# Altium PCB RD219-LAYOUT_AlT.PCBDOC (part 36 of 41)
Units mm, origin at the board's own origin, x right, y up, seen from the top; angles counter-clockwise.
Board outline 209.75 x 159.97 mm, 2 copper layers (TOP, BOTTOM), stack 0 mm thick; 398 components, 199 nets, 1469 pads, 0 vias.
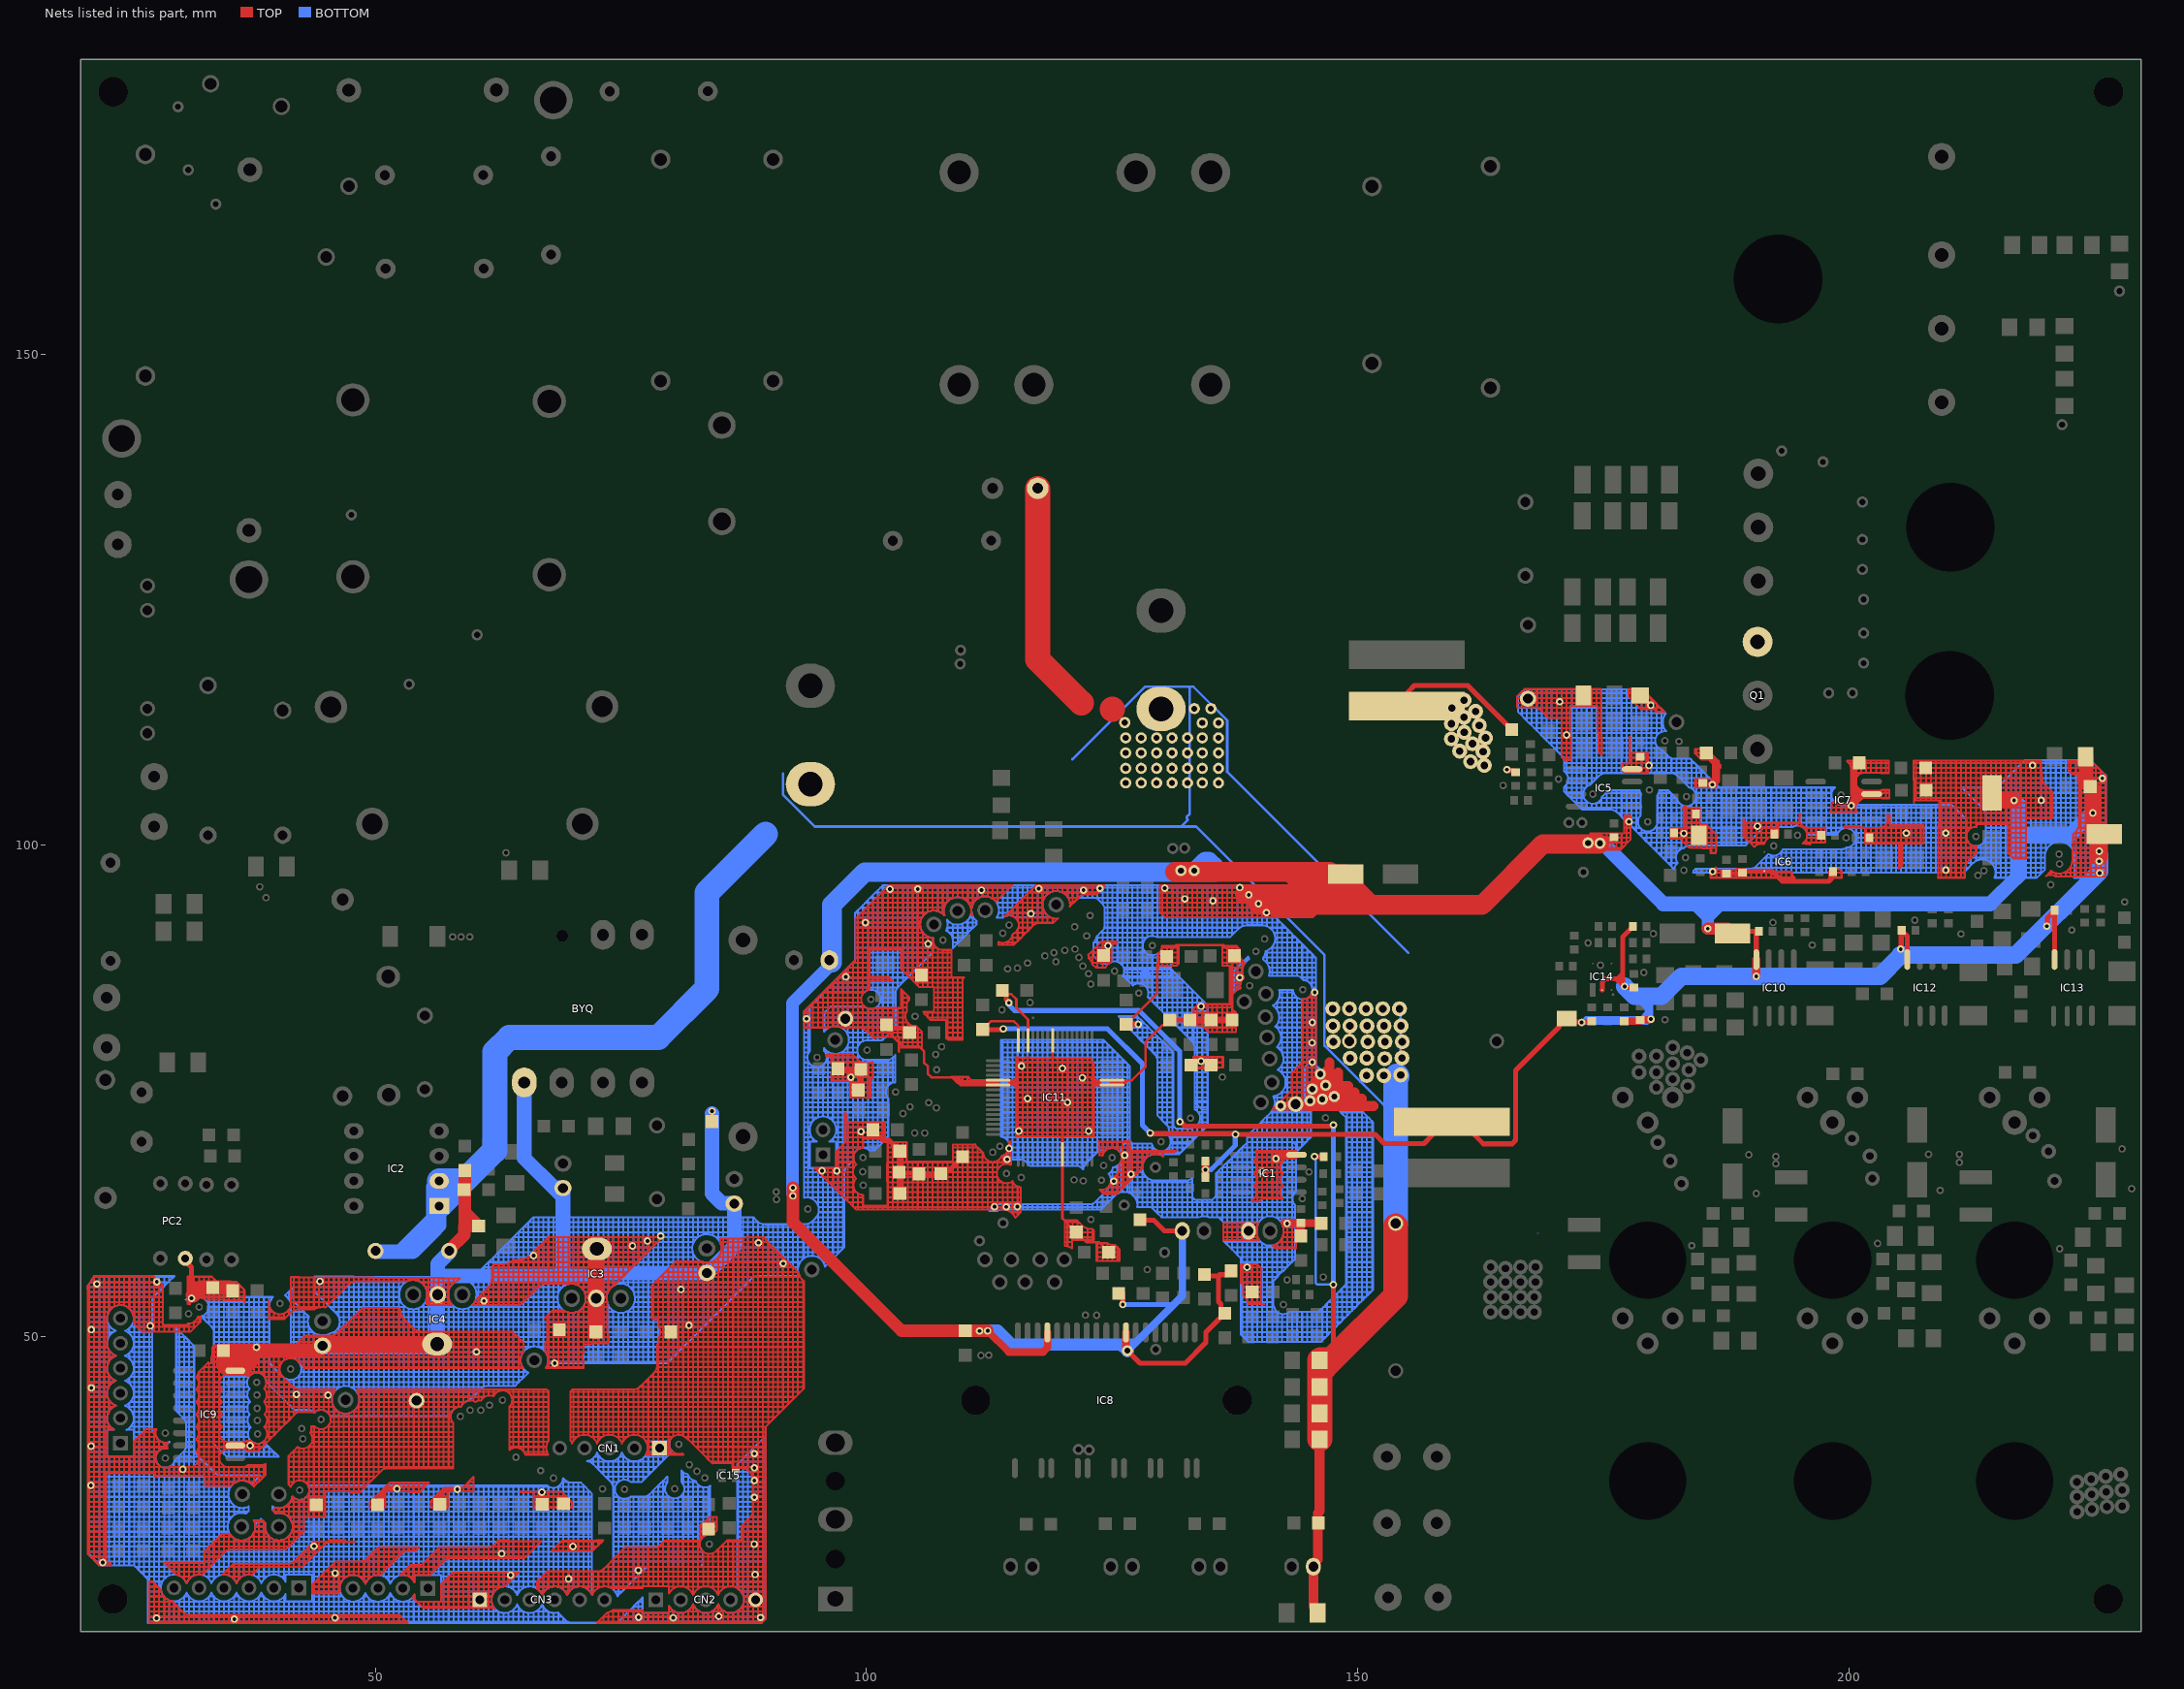
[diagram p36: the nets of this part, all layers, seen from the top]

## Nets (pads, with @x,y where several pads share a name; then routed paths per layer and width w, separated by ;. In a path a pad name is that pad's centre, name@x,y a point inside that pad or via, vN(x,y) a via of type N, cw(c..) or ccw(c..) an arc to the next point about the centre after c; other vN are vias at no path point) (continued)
GND: (continued)
  BOTTOM w0.203: 173.289,108.392 173.289,108.9 ; 173.289,108.392 173.797,108.392 ; 173.289,108.9 173.797,108.9 ; 173.289,108.9 173.289,109.408 ; 173.289,109.408 173.797,109.408 ; 173.289,109.408 173.289,109.916 ; 173.289,109.916 173.797,109.916 ; 173.289,109.916 173.289,110.424 ; 173.289,110.424 173.797,110.424 ; 173.289,110.424 173.289,110.932 ; 173.289,110.932 173.797,110.932 ; 173.289,110.932 173.289,111.44 ; 173.289,111.44 173.797,111.44 ; 173.289,111.44 173.289,111.948 ; 173.289,111.948 173.797,111.948 ; 173.289,111.948 173.289,112.456 ; 173.289,112.456 173.797,112.456 ; 173.289,112.456 173.289,112.964 ; 173.289,112.964 173.797,112.964 ; 173.289,112.964 173.289,113.472 ; 173.289,113.472 173.797,113.472 ; 173.289,113.472 173.289,113.98 ; 173.289,113.98 173.797,113.98 ; 173.289,113.98 173.289,114.488 ; 173.289,114.488 173.797,114.488 ; 173.289,114.488 173.289,114.996 ; 173.289,114.996 173.797,114.996 ; 173.289,114.996 173.289,115.504 ; 173.289,115.504 173.797,115.504 ; 173.289,115.504 173.289,115.885 ; 173.289,115.885 173.797,115.885 ; 173.505,104.328 ccw(c173.924,105.217) 173.797,104.243 ; 173.797,103.667 173.797,103.82 ; 173.797,103.667 174.305,103.667 ; 173.797,103.82 174.305,103.82 ; 173.797,103.82 173.797,104.243 ; 173.797,104.243 ccw(c173.924,105.217) 173.804,104.242 ccw(c173.924,105.217) 174.305,104.311 ; 173.797,106.3 173.797,106.36 ; 173.797,106.3 173.857,106.36 ; 173.797,106.36 173.797,106.868 ; 173.797,106.36 173.857,106.36 ; 173.797,106.868 173.797,107.376 ; 173.797,106.868 174.305,106.868 ; 173.797,107.376 173.797,107.884 ; 173.797,107.376 174.305,107.376 ; 173.797,107.884 173.797,108.392 ; 173.797,107.884 174.305,107.884 ; 173.797,108.392 173.797,108.9 ; 173.797,108.392 174.305,108.392 ; 173.797,108.9 174.305,108.9 ; 173.797,108.9 173.797,109.408 ; 173.797,109.408 174.305,109.408 ; 173.797,109.408 173.797,109.916 ; 173.797,109.916 174.305,109.916 ; 173.797,109.916 173.797,110.424 ; 173.797,110.424 174.305,110.424 ; 173.797,110.424 173.797,110.932 ; 173.797,110.932 174.305,110.932 ; 173.797,110.932 173.797,111.44 ; 173.797,111.44 174.305,111.44 ; 173.797,111.44 173.797,111.948 ; 173.797,111.948 174.305,111.948 ; 173.797,111.948 173.797,112.456 ; 173.797,112.456 174.305,112.456 ; 173.797,112.456 173.797,112.964 ; 173.797,112.964 174.305,112.964 ; 173.797,112.964 173.797,113.472 ; 173.797,113.472 174.305,113.472 ; 173.797,113.472 173.797,113.98 ; 173.797,113.98 174.305,113.98 ; 173.797,113.98 173.797,114.488 ; 173.797,114.488 174.305,114.488 ; 173.797,114.488 173.797,114.996 ; 173.797,114.996 174.305,114.996 ; 173.797,114.996 173.797,115.504 ; 173.797,115.504 174.305,115.504 ; 173.797,115.504 173.797,115.885 ; 173.797,115.885 174.305,115.885 ; 173.857,106.36 174.305,106.808 ; 174.305,103.667 174.813,103.667 ; 174.305,103.667 174.305,103.82 ; 174.305,103.82 174.813,103.82 ; 174.305,103.82 174.305,104.311 ; 174.305,104.311 ccw(c173.924,105.217) 174.343,104.328 ; 174.305,106.808 174.305,106.868 ; 174.305,106.808 174.365,106.868 ; 174.305,106.868 174.305,107.376 ; 174.305,106.868 174.365,106.868 ; 174.305,107.376 174.305,107.884 ; 174.305,107.376 174.813,107.376 ; 174.305,107.884 174.305,108.392 ; 174.305,107.884 174.813,107.884 ; 174.305,108.392 174.305,108.9 ; 174.305,108.392 174.813,108.392 ; 174.305,108.9 174.813,108.9 ; 174.305,108.9 174.305,109.408 ; 174.305,109.408 174.813,109.408 ; 174.305,109.408 174.305,109.916 ; 174.305,109.916 174.813,109.916 ; 174.305,109.916 174.305,110.424 ; 174.305,110.424 174.813,110.424 ; 174.305,110.424 174.305,110.932 ; 174.305,110.932 174.813,110.932 ; 174.305,110.932 174.305,111.44 ; 174.305,111.44 174.813,111.44 ; 174.305,111.44 174.305,111.948 ; 174.305,111.948 174.813,111.948 ; 174.305,111.948 174.305,112.456 ; 174.305,112.456 174.813,112.456 ; 174.305,112.456 174.305,112.964 ; 174.305,112.964 174.813,112.964 ; 174.305,112.964 174.305,113.472 ; 174.305,113.472 174.813,113.472 ; 174.305,113.472 174.305,113.98 ; 174.305,113.98 174.813,113.98 ; 174.305,113.98 174.305,114.488 ; 174.305,114.488 174.813,114.488 ; 174.305,114.488 174.305,114.996 ; 174.305,114.996 174.813,114.996 ; 174.305,114.996 174.305,115.504 ; 174.305,115.504 174.813,115.504 ; 174.305,115.504 174.305,115.885 ; 174.305,115.885 174.813,115.885 ; 174.343,104.328 ccw(c173.924,105.217) 174.813,104.798 ; 174.343,104.328 174.813,104.328 ; 174.365,106.868 174.589,107.092 ; 174.589,107.092 cw(c175.194,106.487) 174.813,107.253 ; 174.589,107.092 cw(c175.194,106.487) 174.813,107.253 ; 174.813,103.667 174.813,103.82 ; 174.813,103.667 175.321,103.667 ; 174.813,103.82 174.813,104.328 ; 174.813,103.82 175.321,103.82 ; 174.813,104.328 175.321,104.328 ; 174.813,104.328 174.813,104.798 ; 174.813,104.798 ccw(c173.924,105.217) 174.83,104.836 ; 174.813,107.253 cw(c175.194,106.487) 175.194,107.343 ; 174.813,107.253 cw(c175.194,106.487) 175.194,107.343 ; 174.813,107.253 174.813,107.376 ; 174.813,107.376 174.813,107.884 ; 174.813,107.376 175.321,107.376 ; 174.813,107.884 174.813,108.392 ; 174.813,107.884 175.321,107.884 ; 174.813,108.392 174.813,108.9 ; 174.813,108.392 175.321,108.392 ; 174.813,108.9 175.321,108.9 ; 174.813,108.9 174.813,109.408 ; 174.813,109.408 175.321,109.408 ; 174.813,109.408 174.813,109.916 ; 174.813,109.916 175.321,109.916 ; 174.813,109.916 174.813,110.424 ; 174.813,110.424 175.321,110.424 ; 174.813,110.424 174.813,110.932 ; 174.813,110.932 175.321,110.932 ; 174.813,110.932 174.813,111.44 ; 174.813,111.44 175.321,111.44 ; 174.813,111.44 174.813,111.948 ; 174.813,111.948 175.321,111.948 ; 174.813,111.948 174.813,112.456 ; 174.813,112.456 175.321,112.456 ; 174.813,112.456 174.813,112.964 ; 174.813,112.964 175.321,112.964 ; 174.813,112.964 174.813,113.472 ; 174.813,113.472 175.321,113.472 ; 174.813,113.472 174.813,113.98 ; 174.813,113.98 175.321,113.98 ; 174.813,113.98 174.813,114.488 ; 174.813,114.488 175.321,114.488 ; 174.813,114.488 174.813,114.996 ; 174.813,114.996 175.321,114.996 ; 174.813,114.996 174.813,115.504 ; 174.813,115.504 175.321,115.504 ; 174.813,115.504 174.813,115.885 ; 174.813,115.885 175.321,115.885 ; 174.83,104.836 175.321,104.836 ; 175.194,107.343 175.321,107.343 ; 175.261,105.344 175.321,105.344 ; 175.261,105.344 175.321,105.404 ; 175.321,103.667 175.321,103.82 ; 175.321,103.667 175.545,103.667 ; 175.321,103.82 175.321,104.328 ; 175.321,103.82 175.829,103.82 ; 175.321,104.328 175.321,104.836 ; 175.321,104.328 175.829,104.328 ; 175.321,104.836 175.829,104.836 ; 175.321,104.836 175.321,105.344 ; 175.321,105.344 175.829,105.344 ; 175.321,105.344 175.321,105.404 ; 175.321,105.404 175.548,105.631 175.829,105.631 ; 175.321,107.343 175.321,107.376 ; 175.321,107.343 175.829,107.343 ; 175.321,107.376 175.321,107.884 ; 175.321,107.376 175.829,107.376 ; 175.321,107.884 175.321,108.392 ; 175.321,107.884 175.829,107.884 ; 175.321,108.392 175.321,108.9 ; 175.321,108.392 175.829,108.392 ; 175.321,108.9 175.321,109.408 ; 175.321,108.9 175.829,108.9 ; 175.321,109.408 175.321,109.916 ; 175.321,109.408 175.829,109.408 ; 175.321,109.916 175.321,110.424 ; 175.321,109.916 175.829,109.916 ; 175.321,110.424 175.321,110.932 ; 175.321,110.424 175.829,110.424 ; 175.321,110.932 175.321,111.44 ; 175.321,110.932 175.829,110.932 ; 175.321,111.44 175.321,111.948 ; 175.321,111.44 175.829,111.44 ; 175.321,111.948 175.321,112.456 ; 175.321,111.948 175.829,111.948 ; 175.321,112.456 175.321,112.964 ; 175.321,112.456 175.829,112.456 ; 175.321,112.964 175.321,113.472 ; 175.321,112.964 175.829,112.964 ; 175.321,113.472 175.321,113.98 ; 175.321,113.472 175.829,113.472 ; 175.321,113.98 175.321,114.488 ; 175.321,113.98 175.829,113.98 ; 175.321,114.488 175.321,114.996 ; 175.321,114.488 175.829,114.488 ; 175.321,114.996 175.321,115.504 ; 175.321,114.996 175.829,114.996 ; 175.321,115.504 175.321,115.885 ; 175.321,115.504 175.829,115.504 ; 175.321,115.885 175.829,115.885 ; 175.545,103.667 cw(c175.545,102.315) 175.826,103.637 ; 175.545,103.667 cw(c175.545,102.315) 175.826,103.637 ; 175.826,103.637 cw(c175.545,102.315) 175.829,103.637 ; 175.826,103.637 cw(c175.545,102.315) 175.829,103.637 ; 175.829,103.637 cw(c175.545,102.315) 176.337,103.411 ; 175.829,103.637 cw(c175.545,102.315) 176.337,103.411 ; 175.829,103.637 175.829,103.82 ; 175.829,103.82 176.337,103.82 ; 175.829,103.82 175.829,104.328 ; 175.829,104.328 175.829,104.836 ; 175.829,104.328 176.337,104.328 ; 175.829,104.836 176.337,104.836 ; 175.829,104.836 175.829,105.344 ; 175.829,105.344 176.337,105.344 ; 175.829,105.344 175.829,105.631 ; 175.829,105.631 176.337,105.631 ; 175.829,107.343 175.829,107.376 ; 175.829,107.343 176.337,107.343 ; 175.829,107.376 175.829,107.884 ; 175.829,107.376 176.337,107.376 ; 175.829,107.884 175.829,108.392 ; 175.829,107.884 176.337,107.884 ; 175.829,108.392 175.829,108.9 ; 175.829,108.392 176.337,108.392 ; 175.829,108.9 175.829,109.408 ; 175.829,108.9 176.337,108.9 ; 175.829,109.408 175.829,109.916 ; 175.829,109.408 176.337,109.408 ; 175.829,109.916 175.829,110.424 ; 175.829,109.916 176.337,109.916 ; 175.829,110.424 175.829,110.932 ; 175.829,110.424 176.337,110.424 ; 175.829,110.932 175.829,111.44 ; 175.829,110.932 176.337,110.932 ; 175.829,111.44 175.829,111.948 ; 175.829,111.44 176.337,111.44 ; 175.829,111.948 175.829,112.456 ; 175.829,111.948 176.337,111.948 ; 175.829,112.456 175.829,112.964 ; 175.829,112.456 176.337,112.456 ; 175.829,112.964 175.829,113.472 ; 175.829,112.964 176.337,112.964 ; 175.829,113.472 175.829,113.98 ; 175.829,113.472 176.337,113.472 ; 175.829,113.98 175.829,114.488 ; 175.829,113.98 176.337,113.98 ; 175.829,114.488 175.829,114.996 ; 175.829,114.488 176.337,114.488 ; 175.829,114.996 175.829,115.504 ; 175.829,114.996 176.337,114.996 ; 175.829,115.504 175.829,115.885 ; 175.829,115.504 176.337,115.504 ; 175.829,115.885 176.337,115.885 ; 176.337,103.411 cw(c175.545,102.315) 176.458,103.312 ; 176.337,103.411 cw(c175.545,102.315) 176.458,103.312 ; 176.337,103.411 176.337,103.82 ; 176.337,103.82 176.337,104.328 ; 176.337,103.82 176.845,103.82 ; 176.337,104.328 176.337,104.836 ; 176.337,104.328 176.845,104.328 ; 176.337,104.836 176.845,104.836 ; 176.337,104.836 176.337,105.344 ; 176.337,105.344 176.845,105.344 ; 176.337,105.344 176.337,105.631 ; 176.337,105.631 176.845,105.631 ; 176.337,107.343 176.337,107.376 ; 176.337,107.343 176.845,107.343 ; 176.337,107.376 176.337,107.884 ; 176.337,107.376 176.845,107.376 ; 176.337,107.884 176.337,108.392 ; 176.337,107.884 176.845,107.884 ; 176.337,108.392 176.337,108.9 ; 176.337,108.392 176.845,108.392 ; 176.337,108.9 176.337,109.408 ; 176.337,108.9 176.845,108.9 ; 176.337,109.408 176.337,109.916 ; 176.337,109.408 176.845,109.408 ; 176.337,109.916 176.337,110.424 ; 176.337,109.916 176.845,109.916 ; 176.337,110.424 176.337,110.932 ; 176.337,110.424 176.845,110.424 ; 176.337,110.932 176.337,111.44 ; 176.337,110.932 176.845,110.932 ; 176.337,111.44 176.337,111.948 ; 176.337,111.44 176.845,111.44 ; 176.337,111.948 176.337,112.456 ; 176.337,111.948 176.845,111.948 ; 176.337,112.456 176.337,112.964 ; 176.337,112.456 176.845,112.456 ; 176.337,112.964 176.337,113.472 ; 176.337,112.964 176.845,112.964 ; 176.337,113.472 176.337,113.98 ; 176.337,113.472 176.845,113.472 ; 176.337,113.98 176.337,114.488 ; 176.337,113.98 176.845,113.98 ; 176.337,114.488 176.337,114.996 ; 176.337,114.488 176.845,114.488 ; 176.337,114.996 176.337,115.504 ; 176.337,114.996 176.845,114.996 ; 176.337,115.504 176.337,115.885 ; 176.337,115.504 176.845,115.504 ; 176.337,115.885 176.845,115.885 ; 176.458,103.312 cw(c175.545,102.315) 176.501,103.271 ccw(c175.545,102.315) 176.458,103.312 ; 176.458,103.312 176.845,103.312 ; 176.845,102.927 176.968,102.804 ; 176.845,102.927 176.845,103.312 ; 176.845,103.312 176.845,103.82 ; 176.845,103.312 177.353,103.312 ; 176.845,103.82 176.845,104.328 ; 176.845,103.82 177.353,103.82 ; 176.845,104.328 176.845,104.836 ; 176.845,104.328 177.353,104.328 ; 176.845,104.836 176.845,105.344 ; 176.845,104.836 177.353,104.836 ; 176.845,105.344 176.845,105.631 ; 176.845,105.344 177.353,105.344 ; 176.845,105.631 177.353,105.631 ; 176.845,107.343 176.845,107.376 ; 176.845,107.343 177.353,107.343 ; 176.845,107.376 176.845,107.884 ; 176.845,107.376 177.353,107.376 ; 176.845,107.884 176.845,108.392 ; 176.845,107.884 177.353,107.884 ; 176.845,108.392 176.845,108.9 ; 176.845,108.392 177.353,108.392 ; 176.845,108.9 176.845,109.408 ; 176.845,108.9 177.353,108.9 ; 176.845,109.408 176.845,109.916 ; 176.845,109.408 177.353,109.408 ; 176.845,109.916 176.845,110.424 ; 176.845,109.916 177.353,109.916 ; 176.845,110.424 176.845,110.932 ; 176.845,110.424 177.353,110.424 ; 176.845,110.932 176.845,111.44 ; 176.845,110.932 177.353,110.932 ; 176.845,111.44 176.845,111.948 ; 176.845,111.44 177.353,111.44 ; 176.845,111.948 176.845,112.456 ; 176.845,111.948 177.353,111.948 ; 176.845,112.456 176.845,112.964 ; 176.845,112.456 177.353,112.456 ; 176.845,112.964 176.845,113.472 ; 176.845,112.964 177.353,112.964 ; 176.845,113.472 176.845,113.98 ; 176.845,113.472 177.353,113.472 ; 176.845,113.98 176.845,114.488 ; 176.845,113.98 177.353,113.98 ; 176.845,114.488 176.845,114.996 ; 176.845,114.488 177.353,114.488 ; 176.845,114.996 176.845,115.504 ; 176.845,114.996 177.353,114.996 ; 176.845,115.504 176.845,115.885 ; 176.845,115.504 177.353,115.504 ; 176.845,115.885 177.353,115.885 ; 176.968,102.804 pad.@177.353,102.419 ; 176.968,102.804 177.353,102.804 ; pad.@177.353,102.419 pad.@177.476,102.296 ; pad.@177.353,102.419 177.353,102.804 ; 177.353,102.804 177.353,103.312 ; 177.353,102.804 177.861,102.804 ; 177.353,103.312 177.353,103.82 ; 177.353,103.312 177.861,103.312 ; 177.353,103.82 177.353,104.328 ; 177.353,103.82 177.861,103.82 ; 177.353,104.328 177.353,104.836 ; 177.353,104.328 177.861,104.328 ; 177.353,104.836 177.353,105.344 ; 177.353,104.836 177.861,104.836 ; 177.353,105.344 177.353,105.631 ; 177.353,105.344 177.861,105.344 ; 177.353,105.631 177.861,105.631 ; 177.353,107.343 177.353,107.376 ; 177.353,107.343 177.861,107.343 ; 177.353,107.376 177.353,107.884 ; 177.353,107.376 177.861,107.376 ; 177.353,107.884 177.353,108.392 ; 177.353,107.884 177.861,107.884 ; 177.353,108.392 177.353,108.9 ; 177.353,108.392 177.861,108.392 ; 177.353,108.9 177.353,109.408 ; 177.353,108.9 177.861,108.9 ; 177.353,109.408 177.353,109.916 ; 177.353,109.408 177.861,109.408 ; 177.353,109.916 177.353,110.424 ; 177.353,109.916 177.861,109.916 ; 177.353,110.424 177.353,110.932 ; 177.353,110.424 177.861,110.424 ; 177.353,110.932 177.353,111.44 ; 177.353,110.932 177.861,110.932 ; 177.353,111.44 177.353,111.948 ; 177.353,111.44 177.861,111.44 ; 177.353,111.948 177.353,112.456 ; 177.353,111.948 177.861,111.948 ; 177.353,112.456 177.353,112.964 ; 177.353,112.456 177.861,112.456 ; 177.353,112.964 177.353,113.472 ; 177.353,112.964 177.861,112.964 ; 177.353,113.472 177.353,113.98 ; 177.353,113.472 177.861,113.472 ; 177.353,113.98 177.353,114.488 ; 177.353,113.98 177.861,113.98 ; 177.353,114.488 177.353,114.996 ; 177.353,114.488 177.861,114.488 ; 177.353,114.996 177.353,115.504 ; 177.353,114.996 177.861,114.996 ; 177.353,115.504 177.353,115.885 ; 177.353,115.504 177.861,115.504 ; 177.353,115.885 177.861,115.885 ; pad.@177.476,102.296 177.861,101.911 ; pad.@177.476,102.296 pad.@177.861,102.296 ; 177.861,101.911 177.984,101.788 ; 177.861,101.911 pad.@177.861,102.296 ; pad.@177.861,102.296 178.369,102.296 ; pad.@177.861,102.296 177.861,102.804 ; 177.861,102.804 177.861,103.312 ; 177.861,102.804 178.369,102.804 ; 177.861,103.312 177.861,103.82 ; 177.861,103.312 178.369,103.312 ; 177.861,103.82 177.861,104.328 ; 177.861,103.82 178.369,103.82 ; 177.861,104.328 177.861,104.836 ; 177.861,104.328 178.369,104.328 ; 177.861,104.836 177.861,105.344 ; 177.861,104.836 178.369,104.836 ; 177.861,105.344 177.861,105.631 ; 177.861,105.344 178.369,105.344 ; 177.861,105.631 178.369,105.631 ; 177.861,107.343 177.861,107.376 ; 177.861,107.343 178.369,107.343 ; 177.861,107.376 177.861,107.884 ; 177.861,107.376 178.369,107.376 ; 177.861,107.884 177.861,108.392 ; 177.861,107.884 178.369,107.884 ; 177.861,108.392 177.861,108.9 ; 177.861,108.392 178.369,108.392 ; 177.861,108.9 177.861,109.408 ; 177.861,108.9 178.369,108.9 ; 177.861,109.408 177.861,109.916 ; 177.861,109.408 178.369,109.408 ; 177.861,109.916 177.861,110.424 ; 177.861,109.916 178.369,109.916 ; 177.861,110.424 177.861,110.932 ; 177.861,110.424 178.369,110.424 ; 177.861,110.932 177.861,111.44 ; 177.861,110.932 178.369,110.932 ; 177.861,111.44 177.861,111.948 ; 177.861,111.44 178.369,111.44 ; 177.861,111.948 177.861,112.456 ; 177.861,111.948 178.369,111.948 ; 177.861,112.456 177.861,112.964 ; 177.861,112.456 178.369,112.456 ; 177.861,112.964 177.861,113.472 ; 177.861,112.964 178.369,112.964 ; 177.861,113.472 177.861,113.98 ; 177.861,113.472 178.369,113.472 ; 177.861,113.98 177.861,114.488 ; 177.861,113.98 178.369,113.98 ; 177.861,114.488 177.861,114.996 ; 177.861,114.488 178.369,114.488 ; 177.861,114.996 177.861,115.504 ; 177.861,114.996 178.369,114.996 ; 177.861,115.504 177.861,115.885 ; 177.861,115.504 178.369,115.504 ; 177.861,115.885 178.369,115.885 ; 177.984,101.788 178.369,101.403 ; 177.984,101.788 178.369,101.788 ; 178.369,101.403 178.492,101.28 ; 178.369,101.403 178.369,101.788 ; 178.369,101.788 178.369,102.296 ; 178.369,101.788 178.731,101.788 ; 178.369,102.296 178.369,102.804 ; 178.369,102.296 178.526,102.296 ; 178.369,102.804 178.369,103.312 ; 178.369,102.804 178.61,102.804 ; 178.369,103.312 178.369,103.82 ; 178.369,103.312 178.783,103.312 ; 178.369,103.82 178.369,104.328 ; 178.369,103.82 178.783,103.82 ; 178.369,104.328 178.369,104.836 ; 178.369,104.328 178.783,104.328 ; 178.369,104.836 178.369,105.344 ; 178.369,104.836 178.783,104.836 ; 178.369,105.344 178.369,105.631 ; 178.369,105.344 178.741,105.344 ; 178.369,105.631 178.698,105.631 ccw(c179.68,105.633) 178.741,105.344 ; 178.369,107.343 178.369,107.376 ; 178.369,107.343 178.877,107.343 ; 178.369,107.376 178.369,107.884 ; 178.369,107.376 178.877,107.376 ; 178.369,107.884 178.369,108.392 ; 178.369,107.884 178.877,107.884 ; 178.369,108.392 178.369,108.9 ; 178.369,108.392 178.877,108.392 ; 178.369,108.9 178.369,109.408 ; 178.369,108.9 178.877,108.9 ; 178.369,109.408 178.369,109.916 ; 178.369,109.408 178.877,109.408 ; 178.369,109.916 178.369,110.424 ; 178.369,109.916 178.877,109.916 ; 178.369,110.424 178.369,110.932 ; 178.369,110.424 178.877,110.424 ; 178.369,110.932 178.369,111.44 ; 178.369,110.932 178.877,110.932 ; 178.369,111.44 178.369,111.948 ; 178.369,111.44 178.877,111.44 ; 178.369,111.948 178.369,112.456 ; 178.369,111.948 178.877,111.948 ; 178.369,112.456 178.369,112.964 ; 178.369,112.456 178.877,112.456 ; 178.369,112.964 178.369,113.472 ; 178.369,112.964 178.877,112.964 ; 178.369,113.472 178.369,113.98 ; 178.369,113.472 178.877,113.472 ; 178.369,113.98 178.369,114.488 ; 178.369,113.98 178.877,113.98 ; 178.369,114.488 178.369,114.996 ; 178.369,114.488 178.877,114.488 ; 178.369,114.996 178.369,115.504 ; 178.369,114.996 178.877,114.996 ; 178.369,115.504 178.369,115.885 ; 178.369,115.504 178.877,115.504 ; 178.369,115.885 178.877,115.885 ; 178.492,101.28 178.877,100.895 ; 178.492,101.28 178.877,101.28 ; 178.526,102.296 ccw(c179.503,102.395) 178.729,101.79 ccw(c179.503,102.395) 178.731,101.788 ; 178.526,102.296 cw(c179.503,102.395) 178.521,102.395 cw(c179.503,102.395) 178.61,102.804 ; 178.61,102.804 cw(c179.503,102.395) 178.613,102.81 cw(c179.503,102.395) 178.783,103.064 ; 178.731,101.788 ccw(c179.503,102.395) 178.872,101.642 ccw(c179.503,102.395) 178.877,101.638 ; 178.783,103.064 178.783,103.312 ; 178.783,103.312 178.783,103.82 ; 178.783,103.82 178.783,104.328 ; 178.783,104.328 178.783,104.836 ; 178.877,100.895 179,100.772 ; 178.877,100.895 178.877,101.28 ; 178.877,101.28 179.385,101.28 ; 178.877,101.28 178.877,101.638 ; 178.877,101.638 ccw(c179.503,102.395) 179.385,101.42 ; 178.877,107.343 178.877,107.376 ; 178.877,107.343 179.385,107.343 ; 178.877,107.376 178.877,107.884 ; 178.877,107.376 179.385,107.376 ; 178.877,107.884 178.877,108.392 ; 178.877,107.884 pad.@179.385,107.884 ; 178.877,108.392 178.877,108.9 ; 178.877,108.392 pad.@179.385,108.392 ; 178.877,108.9 178.877,109.408 ; 178.877,108.9 179.385,108.9 ; 178.877,109.408 178.877,109.916 ; 178.877,109.408 179.385,109.408 ; 178.877,109.916 178.877,110.424 ; 178.877,109.916 179.385,109.916 ; 178.877,110.424 178.877,110.932 ; 178.877,110.424 179.385,110.424 ; 178.877,110.932 178.877,111.44 ; 178.877,110.932 179.385,110.932 ; 178.877,111.44 178.877,111.948 ; 178.877,111.44 179.385,111.44 ; 178.877,111.948 178.877,112.456 ; 178.877,111.948 179.385,111.948 ; 178.877,112.456 178.877,112.964 ; 178.877,112.456 179.385,112.456 ; 178.877,112.964 178.877,113.472 ; 178.877,112.964 179.385,112.964 ; 178.877,113.472 178.877,113.98 ; 178.877,113.472 179.385,113.472 ; 178.877,113.98 178.877,114.488 ; 178.877,113.98 179.385,113.98 ; 178.877,114.488 178.877,114.996 ; 178.877,114.488 179.385,114.488 ; 178.877,114.996 178.877,115.504 ; 178.877,114.996 179.385,114.996 ; 178.877,115.504 178.877,115.885 ; 178.877,115.504 179.258,115.504 ; 178.877,115.885 179.258,115.504 ; 179,100.772 179.385,100.387 ; 179,100.772 179.385,100.772 ; 179.258,115.504 179.385,115.377 ; 179.385,100.387 179.508,100.264 ; 179.385,100.387 179.385,100.772 ; 179.385,100.772 179.385,101.28 ; 179.385,100.772 179.893,100.772 ; 179.385,101.28 179.893,101.28 ; 179.385,101.28 179.385,101.42 ; 179.385,101.42 ccw(c179.503,102.395) 179.503,101.412 ccw(c179.503,102.395) 179.893,101.493 ; 179.385,107.343 179.385,107.376 ; 179.385,107.343 179.893,107.343 ; 179.385,107.376 179.893,107.376 ; 179.385,107.376 pad.@179.385,107.884 ; pad.@179.385,107.884 pad.@179.893,107.884 ; pad.@179.385,107.884 pad.@179.385,108.392 ; pad.@179.385,108.392 179.385,108.9 ; pad.@179.385,108.392 pad.@179.893,108.392 ; 179.385,108.9 179.385,109.408 ; 179.385,108.9 179.893,108.9 ; 179.385,109.408 179.385,109.916 ; 179.385,109.408 179.893,109.408 ; 179.385,109.916 179.385,110.424 ; 179.385,109.916 179.893,109.916 ; 179.385,110.424 179.385,110.932 ; 179.385,110.424 179.893,110.424 ; 179.385,110.932 179.385,111.44 ; 179.385,110.932 179.893,110.932 ; 179.385,111.44 179.385,111.948 ; 179.385,111.44 179.893,111.44 ; 179.385,111.948 179.385,112.456 ; 179.385,111.948 179.893,111.948 ; 179.385,112.456 179.385,112.964 ; 179.385,112.456 179.893,112.456 ; 179.385,112.964 179.385,113.472 ; 179.385,112.964 179.893,112.964 ; 179.385,113.472 179.385,113.98 ; 179.385,113.472 179.893,113.472 ; 179.385,113.98 179.385,114.488 ; 179.385,113.98 pad.@179.893,113.98 ; 179.385,114.488 179.385,114.996 ; 179.385,114.488 pad.@179.893,114.488 ; 179.385,114.996 179.385,115.377 ; 179.385,114.996 179.766,114.996 ; 179.385,115.377 179.766,114.996 ; 179.508,100.264 179.893,99.879 ; 179.508,100.264 179.893,100.264 ; 179.766,114.996 179.893,114.869 ; 179.893,99.879 180.016,99.756 ; 179.893,99.879 179.893,100.264 ; 179.893,100.264 179.893,100.772 ; 179.893,100.264 180.401,100.264 ; 179.893,100.772 179.893,101.28 ; 179.893,100.772 180.401,100.772 ; 179.893,101.28 180.401,101.28 ; 179.893,101.28 179.893,101.493 ; 179.893,101.493 ccw(c179.503,102.395) 180.276,101.788 ; 179.893,107.343 179.893,107.376 ; 179.893,107.343 180.401,107.343 ; 179.893,107.376 180.401,107.376 ; 179.893,107.376 pad.@179.893,107.884 ; pad.@179.893,107.884 180.401,107.884 ; pad.@179.893,107.884 pad.@179.893,108.392 ; pad.@179.893,108.392 179.893,108.9 ; pad.@179.893,108.392 180.401,108.392 ; 179.893,108.9 179.893,109.408 ; 179.893,108.9 180.401,108.9 ; 179.893,109.408 179.893,109.916 ; 179.893,109.408 180.401,109.408 ; 179.893,109.916 179.893,110.424 ; 179.893,109.916 180.401,109.916 ; 179.893,110.424 179.893,110.932 ; 179.893,110.424 180.294,110.424 ; 179.893,110.932 179.893,111.44 ; 179.893,110.932 180.315,110.932 ; 179.893,111.44 179.893,111.948 ; 179.893,111.44 180.401,111.44 ; 179.893,111.948 179.893,112.456 ; 179.893,111.948 180.401,111.948 ; 179.893,112.456 179.893,112.964 ; 179.893,112.456 180.401,112.456 ; 179.893,112.964 179.893,113.472 ; 179.893,112.964 180.401,112.964 ; 179.893,113.472 pad.@179.893,113.98 ; 179.893,113.472 180.401,113.472 ; pad.@179.893,113.98 180.401,113.98 ; pad.@179.893,113.98 pad.@179.893,114.488 ; pad.@179.893,114.488 179.893,114.869 ; pad.@179.893,114.488 180.274,114.488 ; 179.893,114.869 180.274,114.488 ; 180.016,99.756 180.401,99.756 ; 180.016,99.756 180.401,99.371 ; 180.274,114.488 180.401,114.361 ; 180.276,101.788 ccw(c179.503,102.395) 180.278,101.79 ccw(c179.503,102.395) 180.401,101.996 ; 180.276,101.788 180.401,101.788 ; 180.294,110.424 ccw(c181.253,110.638) 180.401,110.149 ; 180.294,110.424 cw(c181.253,110.638) 180.315,110.932 ; 180.315,110.932 cw(c181.253,110.638) 180.401,111.128 ; 180.401,99.371 180.401,99.756 ; 180.401,99.371 180.524,99.248 ; 180.401,99.756 180.909,99.756 ; 180.401,99.756 180.401,100.264 ; 180.401,100.264 180.401,100.772 ; 180.401,100.264 180.909,100.264 ; 180.401,100.772 180.401,101.28 ; 180.401,100.772 180.909,100.772 ; 180.401,101.28 180.401,101.788 ; 180.401,101.28 180.909,101.28 ; 180.401,101.788 180.909,101.788 ; 180.401,101.788 180.401,101.996 ; 180.401,101.996 ccw(c179.503,102.395) 180.481,102.296 ; 180.401,107.343 180.909,107.343 ; 180.401,107.343 180.401,107.376 ; 180.401,107.376 180.909,107.376 ; 180.401,107.376 180.401,107.884 ; 180.401,107.884 180.909,107.884 ; 180.401,107.884 180.401,108.392 ; 180.401,108.392 180.909,108.392 ; 180.401,108.392 180.401,108.9 ; 180.401,108.9 180.909,108.9 ; 180.401,108.9 180.401,109.408 ; 180.401,109.408 180.909,109.408 ; 180.401,109.408 180.401,109.916 ; 180.401,109.916 180.587,109.916 ; 180.401,109.916 180.401,110.149 ; 180.401,110.149 ccw(c181.253,110.638) 180.402,110.147 ccw(c181.253,110.638) 180.587,109.916 ; 180.401,111.128 cw(c181.253,110.638) 180.685,111.44 ; 180.401,111.128 180.401,111.44 ; 180.401,111.44 180.401,111.948 ; 180.401,111.44 180.685,111.44 ; 180.401,111.948 180.401,112.456 ; 180.401,111.948 180.909,111.948 ; 180.401,112.456 180.401,112.964 ; 180.401,112.456 180.909,112.456 ; 180.401,112.964 180.401,113.472 ; 180.401,112.964 180.909,112.964 ; 180.401,113.472 180.401,113.98 ; 180.401,113.472 180.909,113.472 ; 180.401,113.98 180.401,114.361 ; 180.401,113.98 180.782,113.98 ; 180.401,114.361 180.782,113.98 ; 180.481,102.296 180.909,102.296 ; 180.495,102.599 cw(c179.639,102.599) 180.484,102.466 ccw(c179.639,102.599) 180.495,102.599 ; 180.495,102.599 180.495,102.804 ; 180.495,102.804 180.495,103.312 ; 180.495,102.804 180.909,102.804 ; 180.495,103.312 180.909,103.312 ; 180.495,103.312 180.495,103.82 ; 180.495,103.82 180.909,103.82 ; 180.495,103.82 180.495,104.328 ; 180.495,104.328 180.495,104.836 ; 180.495,104.328 180.909,104.328 ; 180.495,104.836 180.909,104.836 ; 180.524,99.248 180.909,98.863 ; 180.524,99.248 180.909,99.248 ; 180.587,109.916 ccw(c181.253,110.638) 180.909,109.718 ; 180.619,105.344 ccw(c179.68,105.633) 180.663,105.631 180.909,105.631 ; 180.619,105.344 180.909,105.344 ; 180.685,111.44 cw(c181.253,110.638) 180.909,111.559 ; 180.782,113.98 180.909,113.853 ; 180.909,98.863 181.032,98.74 ; 180.909,98.863 180.909,99.248 ; 180.909,99.248 181.417,99.248 ; 180.909,99.248 180.909,99.756 ; 180.909,99.756 181.417,99.756 ; 180.909,99.756 180.909,100.264 ; 180.909,100.264 180.909,100.772 ; 180.909,100.264 181.417,100.264 ; 180.909,100.772 180.909,101.28 ; 180.909,100.772 181.417,100.772 ; 180.909,101.28 180.909,101.788 ; 180.909,101.28 181.417,101.28 ; 180.909,101.788 180.909,102.296 ; 180.909,101.788 181.417,101.788 ; 180.909,102.296 181.417,102.296 ; 180.909,102.296 180.909,102.804 ; 180.909,102.804 181.417,102.804 ; 180.909,102.804 180.909,103.312 ; 180.909,103.312 180.909,103.82 ; 180.909,103.312 181.417,103.312 ; 180.909,103.82 180.909,104.328 ; 180.909,103.82 181.417,103.82 ; 180.909,104.328 180.909,104.836 ; 180.909,104.328 181.417,104.328 ; 180.909,104.836 181.417,104.836 ; 180.909,104.836 180.909,105.344 ; 180.909,105.344 181.417,105.344 ; 180.909,105.344 180.909,105.631 ; 180.909,105.631 181.417,105.631 ; 180.909,107.343 180.909,107.376 ; 180.909,107.343 181.417,107.343 ; 180.909,107.376 180.909,107.884 ; 180.909,107.376 181.417,107.376 ; 180.909,107.884 180.909,108.392 ; 180.909,107.884 181.417,107.884 ; 180.909,108.392 180.909,108.9 ; 180.909,108.392 181.417,108.392 ; 180.909,108.9 180.909,109.408 ; 180.909,108.9 181.417,108.9 ; 180.909,109.408 181.273,109.408 ; 180.909,109.408 180.909,109.718 ; 180.909,109.718 ccw(c181.253,110.638) 180.99,109.692 ; 180.909,111.559 180.909,111.948 ; 180.909,111.948 180.909,112.456 ; 180.909,111.948 181.164,111.948 ; 180.909,112.456 180.909,112.964 ; 180.909,112.456 181.034,112.456 ; 180.909,112.964 180.909,113.472 ; 180.909,112.964 181.096,112.964 ; 180.909,113.472 180.909,113.853 ; 180.909,113.472 181.29,113.472 ; 180.909,113.853 181.29,113.472 ; 180.99,109.692 181.273,109.408 ; 181.032,98.74 181.417,98.355 ; 181.032,98.74 181.417,98.74 ; 181.034,112.456 ccw(c182.433,112.543) 181.164,111.948 ; 181.034,112.456 cw(c182.433,112.543) 181.096,112.964 ; 181.096,112.964 cw(c182.433,112.543) 181.341,113.421 ; 181.273,109.408 181.417,109.264 ; 181.29,113.472 181.341,113.421 ; 181.417,98.355 181.54,98.232 ; 181.417,98.355 181.417,98.74 ; 181.417,98.74 181.417,99.248 ; 181.417,98.74 181.925,98.74 ; 181.417,99.248 181.925,99.248 ; 181.417,99.248 181.417,99.756 ; 181.417,99.756 181.925,99.756 ; 181.417,99.756 181.417,100.264 ; 181.417,100.264 181.417,100.772 ; 181.417,100.264 181.925,100.264 ; 181.417,100.772 181.417,101.28 ; 181.417,100.772 181.925,100.772 ; 181.417,101.28 181.417,101.788 ; 181.417,101.28 181.925,101.28 ; 181.417,101.788 181.417,102.296 ; 181.417,101.788 181.925,101.788 ; 181.417,102.296 181.417,102.804 ; 181.417,102.296 181.925,102.296 ; 181.417,102.804 181.417,103.312 ; 181.417,102.804 181.925,102.804 ; 181.417,103.312 181.417,103.82 ; 181.417,103.312 181.925,103.312 ; 181.417,103.82 181.417,104.328 ; 181.417,103.82 181.925,103.82 ; 181.417,104.328 181.417,104.836 ; 181.417,104.328 181.925,104.328 ; 181.417,104.836 181.417,105.344 ; 181.417,104.836 181.925,104.836 ; 181.417,105.344 181.858,105.344 ; 181.417,105.344 181.417,105.631 ; 181.417,105.631 181.571,105.631 181.858,105.344 ; 181.417,107.343 181.417,107.376 ; 181.417,107.343 181.925,107.343 ; 181.417,107.376 181.925,107.376 ; 181.417,107.376 181.417,107.884 ; 181.417,107.884 181.925,107.884 ; 181.417,107.884 181.417,108.392 ; 181.417,108.392 181.925,108.392 ; 181.417,108.392 181.417,108.9 ; 181.417,108.9 181.417,109.264 ; 181.417,108.9 181.84,108.9 ; 181.417,109.264 181.624,109.057 ; 181.54,98.232 181.925,98.232 ; 181.54,98.232 181.925,97.847 ; 181.624,109.057 ccw(c182.229,109.662) 181.84,108.9 ; 181.624,109.057 ccw(c182.229,109.662) 181.84,108.9 ; 181.84,108.9 ccw(c182.229,109.662) 181.925,108.862 ; 181.84,108.9 ccw(c182.229,109.662) 181.925,108.862 ; 181.858,105.344 181.925,105.277 ; 181.925,97.847 181.925,98.232 ; 181.925,97.847 182.048,97.724 ; 181.925,98.232 182.433,98.232 ; 181.925,98.232 181.925,98.74 ; 181.925,98.74 181.925,99.248 ; 181.925,98.74 182.373,98.74 ; 181.925,99.248 182.433,99.248 ; 181.925,99.248 181.925,99.756 ; 181.925,99.756 182.433,99.756 ; 181.925,99.756 181.925,100.264 ; 181.925,100.264 181.925,100.772 ; 181.925,100.264 182.433,100.264 ; 181.925,100.772 181.925,101.28 ; 181.925,100.772 182.433,100.772 ; 181.925,101.28 181.925,101.788 ; 181.925,101.28 182.433,101.28 ; 181.925,101.788 181.925,102.296 ; 181.925,101.788 182.433,101.788 ; 181.925,102.296 181.925,102.804 ; 181.925,102.296 182.433,102.296 ; 181.925,102.804 181.925,103.312 ; 181.925,102.804 182.433,102.804 ; 181.925,103.312 181.925,103.82 ; 181.925,103.312 182.433,103.312 ; 181.925,103.82 181.925,104.328 ; 181.925,103.82 182.433,103.82 ; 181.925,104.328 181.925,104.836 ; 181.925,104.328 182.433,104.328 ; 181.925,104.836 181.925,105.277 ; 181.925,104.836 182.366,104.836 ; 181.925,105.277 182.366,104.836 ; 181.925,107.343 cw(c181.925,106.487) 182.433,107.175 ; 181.925,107.343 cw(c181.925,106.487) 182.433,107.175 ; 181.925,107.343 181.925,107.376 ; 181.925,107.376 181.925,107.884 ; 181.925,107.376 182.433,107.376 ; 181.925,107.884 181.925,108.392 ; 181.925,107.884 182.433,107.884 ; 181.925,108.392 182.433,108.392 ; 181.925,108.392 181.925,108.862 ; 181.925,108.862 ccw(c182.229,109.662) 182.229,108.806 ; 181.925,108.862 ccw(c182.229,109.662) 182.229,108.806 ; 182.048,97.724 182.216,97.556 cw(c183.195,97.47) 182.246,97.724 ; 182.048,97.724 182.246,97.724 ; 182.229,108.806 182.433,108.806 ; 182.366,104.836 182.433,104.769 ; 182.373,98.74 ccw(c183.356,98.756) 182.373,98.738 ccw(c183.356,98.756) 182.433,98.418 ; 182.373,98.74 cw(c183.356,98.756) 182.433,99.093 ; 182.433,98.232 182.524,98.232 ; 182.433,98.232 182.433,98.418 ; 182.433,98.418 ccw(c183.356,98.756) 182.524,98.232 ; 182.433,99.093 cw(c183.356,98.756) 182.505,99.248 ; 182.433,99.093 182.433,99.248 ; 182.433,99.248 182.433,99.756 ; 182.433,99.248 182.505,99.248 ; 182.433,99.756 182.941,99.756 ; 182.433,99.756 182.433,100.264 ; 182.433,100.264 182.433,100.772 ; 182.433,100.264 182.941,100.264 ; 182.433,100.772 182.433,101.28 ; 182.433,100.772 182.941,100.772 ; 182.433,101.28 182.433,101.788 ; 182.433,101.28 pad.@182.941,101.28 ; 182.433,101.788 182.433,102.296 ; 182.433,101.788 182.941,101.788 ; 182.433,102.296 182.433,102.804 ; 182.433,102.296 182.941,102.296 ; 182.433,102.804 182.433,103.312 ; 182.433,102.804 182.941,102.804 ; 182.433,103.312 182.433,103.82 ; 182.433,103.312 182.941,103.312 ; 182.433,103.82 182.433,104.328 ; 182.433,103.82 182.941,103.82 ; 182.433,104.328 182.433,104.769 ; 182.433,104.328 182.699,104.328 ; 182.433,107.175 cw(c181.925,106.487) 182.53,107.092 ; 182.433,107.175 cw(c181.925,106.487) 182.53,107.092 ; 182.433,107.175 182.433,107.376 ; 182.433,107.376 182.941,107.376 ; 182.433,107.376 182.433,107.884 ; 182.433,107.884 182.941,107.884 ; 182.433,107.884 182.433,108.392 ; 182.433,108.392 182.941,108.392 ; 182.433,108.392 182.433,108.806 ; 182.433,108.806 182.941,108.806 ; 182.505,99.248 cw(c183.356,98.756) 182.941,99.646 ; 182.53,107.092 182.754,106.868 ; 182.699,104.328 ccw(c183.449,104.963) 182.941,104.122 ; 182.754,106.868 182.941,106.868 ; 182.754,106.868 182.941,106.681 ; 182.941,99.646 182.941,99.756 ; 182.941,99.756 182.941,100.264 ; 182.941,99.756 183.207,99.756 ; 182.941,100.264 182.941,100.772 ; 182.941,100.264 183.449,100.264 ; 182.941,100.772 183.449,100.772 ; 182.941,100.772 pad.@182.941,101.28 ; pad.@182.941,101.28 182.941,101.788 ; pad.@182.941,101.28 pad.@183.449,101.28 ; 182.941,101.788 182.941,102.296 ; 182.941,101.788 183.449,101.788 ; 182.941,102.296 182.941,102.804 ; 182.941,102.296 183.449,102.296 ; 182.941,102.804 182.941,103.312 ; 182.941,102.804 183.449,102.804 ; 182.941,103.312 182.941,103.82 ; 182.941,103.312 183.449,103.312 ; 182.941,103.82 183.449,103.82 ; 182.941,103.82 182.941,104.122 ; 182.941,104.122 ccw(c183.449,104.963) 182.943,104.121 ccw(c183.449,104.963) 183.449,103.98 ; 182.941,106.681 183.262,106.36 ; 182.941,106.681 182.941,106.868 ; 182.941,106.868 182.941,107.376 ; 182.941,106.868 183.449,106.868 ; 182.941,107.376 182.941,107.884 ; 182.941,107.376 183.449,107.376 ; 182.941,107.884 182.941,108.392 ; 182.941,107.884 183.449,107.884 ; 182.941,108.392 182.941,108.806 ; 182.941,108.392 183.449,108.392 ; 182.941,108.806 183.449,108.806 ; 183.207,99.756 ccw(c183.78,99.121) 183.175,99.726 cw(c183.78,99.121) 183.207,99.756 ; 183.207,99.756 cw(c183.78,99.121) 183.446,99.909 ; 183.207,99.756 cw(c183.78,99.121) 183.446,99.909 ; 183.262,106.36 183.449,106.173 ; 183.262,106.36 183.449,106.36 ; 183.446,99.909 cw(c183.78,99.121) 183.449,99.91 ; 183.446,99.909 cw(c183.78,99.121) 183.449,99.91 ; 183.449,99.91 cw(c183.78,99.121) 183.78,99.977 ; 183.449,99.91 cw(c183.78,99.121) 183.78,99.977 ; 183.449,99.91 183.449,100.264 ; 183.449,100.264 183.449,100.772 ; 183.449,100.264 183.957,100.264 ; 183.449,100.772 183.957,100.772 ; 183.449,100.772 pad.@183.449,101.28 ; pad.@183.449,101.28 183.449,101.788 ; pad.@183.449,101.28 183.957,101.28 ; 183.449,101.788 183.449,102.296 ; 183.449,101.788 183.957,101.788 ; 183.449,102.296 183.957,102.296 ; 183.449,102.296 183.449,102.804 ; 183.449,102.804 183.957,102.804 ; 183.449,102.804 183.449,103.312 ; 183.449,103.312 183.449,103.82 ; 183.449,103.312 183.957,103.312 ; 183.449,103.82 183.957,103.82 ; 183.449,103.82 183.449,103.98 ; 183.449,103.98 ccw(c183.449,104.963) 183.957,104.122 ; 183.449,106.173 183.449,106.36 ; 183.449,106.173 183.712,105.91 ; 183.449,106.36 183.957,106.36 ; 183.449,106.36 183.449,106.868 ; 183.449,106.868 183.449,107.376 ; 183.449,106.868 183.957,106.868 ; 183.449,107.376 183.957,107.376 ; 183.449,107.376 183.449,107.884 ; 183.449,107.884 183.957,107.884 ; 183.449,107.884 183.449,108.392 ; 183.449,108.392 183.957,108.392 ; 183.449,108.392 183.449,108.806 ; 183.449,108.806 183.857,108.806 183.957,108.706 ; 183.712,105.91 cw(c183.449,104.963) 183.868,105.852 ; 183.78,99.977 183.957,99.977 ; 183.868,105.852 cw(c183.449,104.963) 183.957,105.804 ; 183.868,105.852 183.957,105.852 ; 183.957,99.977 184.465,99.977 ; 183.957,99.977 183.957,100.264 ; 183.957,100.264 183.957,100.772 ; 183.957,100.264 184.465,100.264 ; 183.957,100.772 183.957,101.28 ; 183.957,100.772 184.465,100.772 ; 183.957,101.28 183.957,101.788 ; 183.957,101.28 184.465,101.28 ; 183.957,101.788 183.957,102.296 ; 183.957,101.788 184.465,101.788 ; 183.957,102.296 183.957,102.804 ; 183.957,102.296 184.465,102.296 ; 183.957,102.804 183.957,103.312 ; 183.957,102.804 184.465,102.804 ; 183.957,103.312 183.957,103.82 ; 183.957,103.312 184.465,103.312 ; 183.957,103.82 184.465,103.82 ; 183.957,103.82 183.957,104.122 ; 183.957,104.122 ccw(c183.449,104.963) 184.199,104.328 ; 183.957,105.804 cw(c183.449,104.963) 184.354,105.347 cw(c183.449,104.963) 184.355,105.344 ; 183.957,105.804 183.957,105.852 ; 183.957,105.852 183.957,106.36 ; 183.957,105.852 184.465,105.852 ; 183.957,106.36 184.465,106.36 ; 183.957,106.36 183.957,106.868 ; 183.957,106.868 183.957,107.376 ; 183.957,106.868 184.465,106.868 ; 183.957,107.376 183.957,107.884 ; 183.957,107.376 184.465,107.376 ; 183.957,107.884 184.465,107.884 ; 183.957,107.884 183.957,108.392 ; 183.957,108.392 183.957,108.706 ; 183.957,108.392 184.271,108.392 ; 183.957,108.706 184.271,108.392 ; 184.199,104.328 ccw(c183.449,104.963) 184.398,104.709 ccw(c183.449,104.963) 184.423,104.836 ; 184.199,104.328 184.465,104.328 ; 184.271,108.392 184.465,108.198 ; 184.355,105.344 cw(c183.449,104.963) 184.432,104.963 cw(c183.449,104.963) 184.423,104.836 ; 184.355,105.344 184.465,105.344 ; 184.423,104.836 184.465,104.836 ; 184.465,97.212 184.465,97.216 ; 184.465,97.212 184.973,97.212 ; 184.465,97.216 184.465,97.63 ; 184.465,97.216 184.973,97.216 ; 184.465,97.63 184.973,97.63 ; 184.465,99.977 184.465,100.264 ; 184.465,99.977 184.973,99.977 ; 184.465,100.264 184.465,100.772 ; 184.465,100.264 184.973,100.264 ; 184.465,100.772 184.465,101.28 ; 184.465,100.772 184.973,100.772 ; 184.465,101.28 184.465,101.788 ; 184.465,101.28 184.973,101.28 ; 184.465,101.788 184.465,102.296 ; 184.465,101.788 184.973,101.788 ; 184.465,102.296 184.465,102.804 ; 184.465,102.296 184.973,102.296 ; 184.465,102.804 184.465,103.312 ; 184.465,102.804 184.973,102.804 ; 184.465,103.312 184.465,103.82 ; 184.465,103.312 184.973,103.312 ; 184.465,103.82 184.465,104.328 ; 184.465,103.82 184.973,103.82 ; 184.465,104.328 184.465,104.836 ; 184.465,104.328 184.973,104.328 ; 184.465,104.836 184.973,104.836 ; 184.465,104.836 184.465,105.344 ; 184.465,105.344 184.465,105.852 ; 184.465,105.344 184.973,105.344 ; 184.465,105.852 184.465,106.36 ; 184.465,105.852 184.973,105.852 ; 184.465,106.36 184.465,106.868 ; 184.465,106.36 184.973,106.36 ; 184.465,106.868 184.465,107.376 ; 184.465,106.868 184.973,106.868 ; 184.465,107.376 184.465,107.884 ; 184.465,107.376 184.973,107.376 ; 184.465,107.884 184.465,108.198 ; 184.465,107.884 184.779,107.884 ; 184.465,108.198 184.779,107.884 ; 184.779,107.884 184.973,107.69 ; 184.973,97.212 184.973,97.216 ; 184.973,97.212 185.481,97.212 ; 184.973,97.216 184.973,97.63 ; 184.973,97.216 185.481,97.216 ; 184.973,97.63 185.481,97.63 ; 184.973,99.977 184.973,100.264 ; 184.973,99.977 185.481,99.977 ; 184.973,100.264 184.973,100.772 ; 184.973,100.264 185.481,100.264 ; 184.973,100.772 184.973,101.28 ; 184.973,100.772 185.481,100.772 ; 184.973,101.28 184.973,101.788 ; 184.973,101.28 185.481,101.28 ; 184.973,101.788 184.973,102.296 ; 184.973,101.788 185.481,101.788 ; 184.973,102.296 184.973,102.804 ; 184.973,102.296 185.481,102.296 ; 184.973,102.804 184.973,103.312 ; 184.973,102.804 185.481,102.804 ; 184.973,103.312 184.973,103.82 ; 184.973,103.312 185.481,103.312 ; 184.973,103.82 184.973,104.328 ; 184.973,103.82 185.481,103.82 ; 184.973,104.328 184.973,104.836 ; 184.973,104.328 185.481,104.328 ; 184.973,104.836 184.973,105.344 ; 184.973,104.836 185.481,104.836 ; 184.973,105.344 184.973,105.852 ; 184.973,105.344 185.481,105.344 ; 184.973,105.852 184.973,106.36 ; 184.973,105.852 185.481,105.852 ; 184.973,106.36 184.973,106.868 ; 184.973,106.36 185.481,106.36 ; 184.973,106.868 184.973,107.376 ; 184.973,106.868 185.481,106.868 ; 184.973,107.376 184.973,107.69 ; 184.973,107.376 185.287,107.376 ; 184.973,107.69 185.287,107.376 ; 185.287,107.376 185.481,107.182 ; 185.481,97.212 185.481,97.216 ; 185.481,97.212 pad.@185.989,97.212 ; 185.481,97.216 185.481,97.63 ; 185.481,97.216 pad.@185.989,97.216 ; 185.481,97.63 pad.@185.989,97.63 ; 185.481,99.977 185.481,100.264 ; 185.481,99.977 185.989,99.977 ; 185.481,100.264 185.481,100.772 ; 185.481,100.264 185.989,100.264 ; 185.481,100.772 185.481,101.28 ; 185.481,100.772 185.989,100.772 ; 185.481,101.28 185.481,101.788 ; 185.481,101.28 185.989,101.28 ; 185.481,101.788 185.481,102.296 ; 185.481,101.788 185.989,101.788 ; 185.481,102.296 185.481,102.804 ; 185.481,102.296 185.989,102.296 ; 185.481,102.804 185.481,103.312 ; 185.481,102.804 185.989,102.804 ; 185.481,103.312 185.481,103.82 ; 185.481,103.312 185.989,103.312 ; 185.481,103.82 185.481,104.328 ; 185.481,103.82 185.989,103.82 ; 185.481,104.328 185.481,104.836 ; 185.481,104.328 185.989,104.328 ; 185.481,104.836 185.481,105.344 ; 185.481,104.836 185.989,104.836 ; 185.481,105.344 185.481,105.852 ; 185.481,105.344 185.989,105.344 ; 185.481,105.852 185.481,106.36 ; 185.481,105.852 pad.@185.989,105.852 ; 185.481,106.36 185.481,106.868 ; 185.481,106.36 pad.@185.989,106.36 ; 185.481,106.868 185.481,107.182 ; 185.481,106.868 185.795,106.868 ; 185.481,107.182 185.795,106.868 ; 185.795,106.868 185.989,106.674 ; pad.@185.989,97.212 pad.@185.989,97.216 ; pad.@185.989,97.212 186.497,97.212 ; pad.@185.989,97.216 186.497,97.216 ; pad.@185.989,97.216 pad.@185.989,97.63 ; pad.@185.989,97.63 186.497,97.63 ; 185.989,99.977 186.497,99.977 ; 185.989,99.977 185.989,100.264 ; 185.989,100.264 185.989,100.772 ; 185.989,100.264 186.497,100.264 ; 185.989,100.772 185.989,101.28 ; 185.989,100.772 186.497,100.772 ; 185.989,101.28 185.989,101.788 ; 185.989,101.28 186.497,101.28 ; 185.989,101.788 185.989,102.296 ; 185.989,101.788 186.497,101.788 ; 185.989,102.296 186.497,102.296 ; 185.989,102.296 185.989,102.804 ; 185.989,102.804 186.497,102.804 ; 185.989,102.804 185.989,103.312 ; 185.989,103.312 185.989,103.82 ; 185.989,103.312 186.497,103.312 ; 185.989,103.82 185.989,104.328 ; 185.989,103.82 186.497,103.82 ; 185.989,104.328 186.497,104.328 ; 185.989,104.328 185.989,104.836 ; 185.989,104.836 186.497,104.836 ; 185.989,104.836 185.989,105.344 ; 185.989,105.344 pad.@185.989,105.852 ; 185.989,105.344 186.497,105.344 ; pad.@185.989,105.852 186.497,105.852 ; pad.@185.989,105.852 pad.@185.989,106.36 ; pad.@185.989,106.36 185.989,106.674 ; pad.@185.989,106.36 pad.@186.303,106.36 ; 185.989,106.674 186.28,106.383 pad.@186.303,106.36 ; pad.@186.303,106.36 186.497,106.166 ; 186.497,97.212 186.497,97.216 ; 186.497,97.212 187.005,97.212 ; 186.497,97.216 187.005,97.216 ; 186.497,97.216 186.497,97.63 ; 186.497,97.63 187.005,97.63 ; 186.497,99.977 187.005,99.977 ; 186.497,99.977 186.497,100.264 ; 186.497,100.264 186.497,100.772 ; 186.497,100.264 187.005,100.264 ; 186.497,100.772 186.497,101.28 ; 186.497,100.772 187.005,100.772 ; 186.497,101.28 186.497,101.788 ; 186.497,101.28 187.005,101.28 ; 186.497,101.788 186.497,102.296 ; 186.497,101.788 187.005,101.788 ; 186.497,102.296 186.497,102.804 ; 186.497,102.296 187.005,102.296 ; 186.497,102.804 186.497,103.312 ; 186.497,102.804 187.005,102.804 ; 186.497,103.312 186.497,103.82 ; 186.497,103.312 187.005,103.312 ; 186.497,103.82 186.497,104.328 ; 186.497,103.82 187.005,103.82 ; 186.497,104.328 187.005,104.328 ; 186.497,104.328 186.497,104.836 ; 186.497,104.836 187.005,104.836 ; 186.497,104.836 186.497,105.344 ; 186.497,105.344 186.497,105.852 ; 186.497,105.344 187.005,105.344 ; 186.497,105.852 186.497,106.166 ; 186.497,105.852 187.005,105.852 ; 186.497,106.166 186.526,106.137 ; 186.526,106.137 ccw(c187.131,106.742) 187.005,105.895 ; 186.526,106.137 ccw(c187.131,106.742) 187.005,105.895 ; 187.005,97.212 187.005,97.216 ; 187.005,97.212 187.513,97.212 ; 187.005,97.216 187.005,97.63 ; 187.005,97.216 187.513,97.216 ; 187.005,97.63 187.513,97.63 ; 187.005,99.977 187.513,99.977 ; 187.005,99.977 187.005,100.264 ; 187.005,100.264 187.005,100.772 ; 187.005,100.264 187.513,100.264 ; 187.005,100.772 187.005,101.28 ; 187.005,100.772 187.513,100.772 ; 187.005,101.28 187.005,101.788 ; 187.005,101.28 187.513,101.28 ; 187.005,101.788 187.005,102.296 ; 187.005,101.788 187.513,101.788 ; 187.005,102.296 187.005,102.804 ; 187.005,102.296 187.513,102.296 ; 187.005,102.804 187.005,103.312 ; 187.005,102.804 187.513,102.804 ; 187.005,103.312 187.005,103.82 ; 187.005,103.312 187.513,103.312 ; 187.005,103.82 187.005,104.328 ; 187.005,103.82 187.513,103.82 ; 187.005,104.328 187.513,104.328 ; 187.005,104.328 187.005,104.836 ; 187.005,104.836 187.513,104.836 ; 187.005,104.836 187.005,105.344 ; 187.005,105.344 187.005,105.852 ; 187.005,105.344 187.513,105.344 ; 187.005,105.852 187.513,105.852 ; 187.005,105.852 187.005,105.895 ; 187.005,105.895 ccw(c187.131,106.742) 187.131,105.886 ; 187.005,105.895 ccw(c187.131,106.742) 187.131,105.886 ; 187.131,105.886 187.513,105.886 ; 187.513,97.212 187.513,97.216 ; 187.513,97.212 188.021,97.212 ; 187.513,97.216 187.513,97.63 ; 187.513,97.216 188.021,97.216 ; 187.513,97.63 188.021,97.63 ; 187.513,99.977 187.513,100.264 ; 187.513,99.977 188.021,99.977 ; 187.513,100.264 187.513,100.772 ; 187.513,100.264 188.021,100.264 ; 187.513,100.772 187.513,101.28 ; 187.513,100.772 188.021,100.772 ; 187.513,101.28 187.513,101.788 ; 187.513,101.28 188.021,101.28 ; 187.513,101.788 187.513,102.296 ; 187.513,101.788 188.021,101.788 ; 187.513,102.296 187.513,102.804 ; 187.513,102.296 188.021,102.296 ; 187.513,102.804 187.513,103.312 ; 187.513,102.804 188.021,102.804 ; 187.513,103.312 187.513,103.82 ; 187.513,103.312 188.021,103.312 ; 187.513,103.82 187.513,104.328 ; 187.513,103.82 188.021,103.82 ; 187.513,104.328 187.513,104.836 ; 187.513,104.328 188.021,104.328 ; 187.513,104.836 187.513,105.344 ; 187.513,104.836 188.021,104.836 ; 187.513,105.344 187.513,105.852 ; 187.513,105.344 188.021,105.344 ; 187.513,105.852 187.513,105.886 ; 187.513,105.852 188.021,105.852 ; 187.513,105.886 188.021,105.886 ; 188.021,97.212 188.021,97.216 ; 188.021,97.212 188.529,97.212 ; 188.021,97.216 188.021,97.63 ; 188.021,97.216 188.529,97.216 ; 188.021,97.63 188.529,97.63 ; 188.021,99.977 188.021,100.264 ; 188.021,99.977 188.529,99.977 ; 188.021,100.264 188.021,100.772 ; 188.021,100.264 188.529,100.264 ; 188.021,100.772 188.021,101.28 ; 188.021,100.772 188.529,100.772 ; 188.021,101.28 188.021,101.788 ; 188.021,101.28 188.529,101.28 ; 188.021,101.788 188.021,102.296 ; 188.021,101.788 188.529,101.788 ; 188.021,102.296 188.021,102.804 ; 188.021,102.296 188.529,102.296 ; 188.021,102.804 188.021,103.312 ; 188.021,102.804 188.529,102.804 ; 188.021,103.312 188.021,103.82 ; 188.021,103.312 188.529,103.312 ; 188.021,103.82 188.021,104.328 ; 188.021,103.82 188.529,103.82 ; 188.021,104.328 188.021,104.836 ; 188.021,104.328 188.529,104.328 ; 188.021,104.836 188.021,105.344 ; 188.021,104.836 188.529,104.836 ; 188.021,105.344 188.021,105.852 ; 188.021,105.344 188.529,105.344 ; 188.021,105.852 188.021,105.886 ; 188.021,105.852 188.529,105.852 ; 188.021,105.886 188.529,105.886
